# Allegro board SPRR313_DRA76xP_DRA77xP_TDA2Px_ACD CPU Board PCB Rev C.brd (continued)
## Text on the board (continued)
User.17: DATE | DESIGN ENGR | PROJECT ENGR | ENGR MGR | NEXT ASSEMBLY | APPROVED | CHECKED | DRAFTING | ENGR | NONE | 1 OF 1 | VIEW | SCALE: NONE | LAYER 7 | LAYER 8 | LAYER 9 | LAYER 10 | LAYER 11 | LAYER 12 | LAYER 13 | LAYER 14 | LAYER 15 | LAYER 16 | LAYER 1 | LAYER 2 | 1.  TOTAL BOARD THICKNESS SHALL BE .080 +/- 10% INCHES. | 2.  REFER TO STACKUP DRAWING FOR COPPER WEIGHT. | 4.  SOLDERMASK ON BOTH SIDES OF THE BOARD SHALL BE S.M.O.B.C., LPI, COLOR GREEN. | 3.  MINIMUM CLEARANCE ON THE BOARD SHALL BE 3.0 MILS. | 5.  PLATED THRU HOLE SIZE TOLERANCES SHALL BE +/- .003 INCH. | 6.  DRC'S MUST BE RUN ON THE GERBERS BEFORE BUILDING BOARDS UNLESS PRIOR | 9.  IMPEDANCE CONTROL: | 7.  FINISHED BOARD SHALL BE FREE OF BURRS ON EDGES. | 8.  SURFACE FINISH SHALL BE IMMERSION GOLD. | AVERAGE COPPER ON THE WALL OF THE | PLATED HOLE SHALL BE PER IPC CLASS 2. | ALL MATERIAL SHALL BE NEMA GRADE FR-4 OR EQUIVALENT. (Tg>=170 DEG. C) | UNPLATED THRU HOLE SIZE TOLERANCES SHALL BE +/- .002 INCH. | MINIMUM TRACE WIDTH ON THE BOARD SHALL BE 3.0 MILS. | APPROVAL IS GIVEN IN WRITING. | REFER TO STACKUP DRAWING FOR IMPEDANCE CONTROL. | NOTES: UNLESS OTHERWISE SPECIFIED | A | A-A
User.18: C100 | R534 | R533 | R535 | R483 | C352 | C347 | C541 | C528 | C484 | C502 | C517 | C504 | C509 | C516 | C477 | C507 | C490 | C491 | C497 | C469 | C508 | C518 | C467 | C498 | C486 | C403 | C343 | R709 | C407 | R513 | R537 | R514 | R516 | C462 | C520 | C458 | C457 | C519 | C471 | C388 | C489 | C512 | C386 | C481 | C495 | C468 | C485 | C475 | C480 | R271 | R273 | C186 | R272 | R274 | C187 | TP64 | R292 | TP61 | TP45 | TP39 | TP52 | R67 | C84 | R736 | R735 | C136 | C96 | C137 | C385 | TP8 | R261 | TP7 | TP10 | TP50 | R256 | C692 | R245 | TP11 | TP51 | TP53 | R658 | TP58 | R237 | R243 | TP14 | TP56 | R231 | U120 | R259 | R263 | TP60 | TP21 | TP26 | R258 | TP19 | TP34 | TP42 | TP43 | C142 | R215 | R553 | C380 | C375 | C353 | C339 | C338 | C432 | C346 | C354 | C341 | R639 | R648 | R655 | R662 | C342 | R395 | R398 | R661 | R666 | C691 | R663 | R640 | R649 | R656 | R542 | R545 | R550 | R556 | R563 | R571 | R582 | R602 | R609 | R613 | R543 | R546 | R551 | R586 | R595 | R598 | R611 | R614 | R572 | R557 | R564 | C649 | R544 | R547 | R552 | R370 | R375 | R377 | R381 | C104 | C412 | C418 | C425 | R632 | C460 | C548 | R376 | C384 | C413 | C419 | C426 | C436 | C368 | C465 | C556 | C367 | C365 | C650 | C483 | C473 | R386 | C265 | C414 | C420 | C427 | C549 | C396 | C400 | C557 | C255 | C369 | C366 | C474 | C466 | C94 | C253 | C91 | R382 | C370 | C260 | C118 | C119 | C392 | R618 | R624 | C92 | C391 | C526 | C482 | C542 | C437 | C444 | C506 | C361 | C501 | C249 | C248 | C245 | C246 | C242 | C478 | R538 | C492 | C439 | C505 | C463 | C127 | C510 | C422 | C429 | C110 | R587 | C479 | C448 | C201 | R214 | TP63 | TP48 | R714 | TP27 | C126 | TP55 | R738 | R740 | R742 | R744 | R746 | R748 | R737 | R739 | R741 | R743 | R745 | R747 | C32 | C171 | R288 | C178 | C185 | R731 | R131 | TP54 | TP59 | R730 | R732 | R110 | R111 | TP9 | R112 | R113 | R114 | R115 | R269 | C159 | R116 | C163 | R289 | TP29 | R120 | R121 | R122 | R123 | R124 | R125 | R191 | R209 | R210 | R211 | C433 | C99 | R193 | C431 | C134 | C101 | C141 | C102 | C103 | R201 | R518 | R708 | C680 | C376 | C379 | R622 | R18 | R16 | R15 | R700 | C642 | C628 | C636 | C664 | C651 | C666 | C667 | C668 | C669 | C562 | C644 | C595 | C630 | R694 | C615 | C652 | C629 | C637 | C401 | R629 | C674 | R625 | C675 | R378 | C523 | C399 | C676 | C677 | C247 | C355 | R399 | C364 | C395 | C500 | C356 | C438 | C496 | C493 | C494 | C537 | C390 | C359 | C363 | C372 | C393 | C445 | C360 | C394 | C398 | C524 | C442 | C90 | C487 | C443 | C397 | C456 | C529 | C89 | C373 | C449 | C530 | C602 | C362 | C589 | C374 | C461 | C371 | C470 | C464 | C402 | 1 | U17 | R291 | J16 | R244 | J2 | TP46 | TP49 | GND | U56 | 2 | USB-ID | U11 | SW1 | C149 | CAN1 | U16 | U12 | C155 | R129 | R133 | R136 | R137 | R139 | 12V-FAN | TP4 | R104 | J7 | R277 | C179 | R98 | R99 | R293 | R178 | U74 | U35 | U54 | C39 | R75 | U41 | J9 | J10 | J12 | TP5 | U48 | C36 | C31 | A1 | U46 | TP65 | TP6 | R200 | R196 | L4 | DCAN1 | JP1 | U36 | U43 | U1 | U9 | C68 | C70 | LEOPARD IMAGING | R27 | R185 | R7 | R1 | T1 | C210 | C73 | C75 | R6 | TP2 | PB/WAKE | Y5 | RU24 | U65 | C203 | C262 | R154 | C80 | Y3 | L8 | C87 | R179 | C682 | C211 | A9 | T9 | USB1 | E1 | C64 | C65 | C106 | E2 | RU31 | C681 | C212 | C113 | R722 | RU40 | E3 | U66 | E9 | C204 | Y6 | U26 | R30 | R33 | R39 | R41 | R47 | R52 | R190 | C213 | R195 | C143 | U15 | R66 | R68 | C107 | C148 | C83 | C59 | U10 | C194 | R96 | C43 | C214 | R61 | C37 | AH1 | AH28 | C40 | R97 | R31 | R34 | R40 | R42 | R48 | R53 | C34 | BGA WITHOUT SKT OUTLINE | U67 | C205 | R183 | U27 | RN2 | C55 | RN6 | RN4 | ETHERNET 0 | C175 | C180 | C165 | RN1 | C147 | U7 | R727 | R728 | R465 | C169 | R729 | R444 | C177 | C184 | R725 | TP12 | R28 | C293 | R468 | C199 | C25 | C26 | A28 | C44 | U68 | C21 | R726 | U18 | R72 | R73 | C41 | C195 | Y1 | E4 | C85 | R132 | R43 | R49 | R54 | ETHERNET 1 | E5 | C24 | R718 | SW2 | R128 | R242 | R56 | TP25 | R44 | R50 | R55 | C67 | R37 | R130 | C30 | E6 | R224 | TP16 | TP20 | TP13 | TP15 | R221 | U69 | R156 | C18 | R38 | RU19 | C196 | C146 | R188 | R189 | R197 | R198 | R202 | R212 | R217 | R235 | R248 | U62 | TP17 | DCAN2 | R199 | R203 | R213 | R218 | R220 | R225 | R232 | RU21 | R717 | JP3 | U61 | C98 | C122 | R2 | U6 | U25 | C135 | R5 | C4 | R286 | R270 | C14 | C176 | U38 | C12 | R3 | R229 | R233 | R268 | R240 | C15 | RU49 | C23 | C69 | C82 | R247 | L1 | JTAG | U2 | R754 | C16 | C2 | R181 | TP62 | R46 | C35 | U39 | R4 | C29 | U118 | U57 | 19 | U14 | R22 | DS1 | DS2 | DS3 | L13 | L3 | U3 | U58 | TP24 | R149 | TP32 | RU5 | E7 | DS4 | LCD CONNECTOR | C60 | L6 | C7 | L9 | R11 | J4 | E8 | C74 | R126 | USER | LEDS | R257 | R260 | R262 | R266 | R144 | R143 | L10 | TP31 | C131 | R472 | C76 | L11 | L19 | C47 | TP30 | U59 | R151 | Y4 | Q1 | Q3 | U37 | F1 | Q4 | R145 | C78 | U51 | Q2 | R147 | R281 | R146 | R234 | R239 | C133 | R287 | U8 | C97 | U55 | C153 | L21 | R440 | R449 | R127 | U47 | TP3 | C51 | C684 | C72 | C77 | C61 | L7 | R619 | R569 | R579 | R585 | R594 | R599 | R601 | R604 | R610 | R612 | R710 | R461 | C304 | C536 | R450 | R701 | C299 | C377 | C349 | U105 | C513 | C329 | C316 | R456 | C63 | C435 | C301 | C306 | R463 | C330 | R580 | R702 | C62 | R453 | C305 | C309 | R697 | C647 | R654 | R659 | R664 | R668 | U90 | R475 | R672 | Q5 | C302 | C326 | R451 | R671 | R464 | C307 | C327 | C215 | C568 | R675 | C575 | C558 | R660 | U91 | R673 | R422 | R423 | R426 | R638 | R647 | R665 | R414 | C328 | R428 | R749 | R674 | R676 | R677 | R682 | R383 | R384 | C236 | R750 | C216 | U106 | R567 | R35 | R751 | C488 | C459 | R332 | C318 | C235 | C333 | C378 | C410 | R474 | C350 | RU82 | U22 | R391 | R596 | C251 | R623 | U107 | R364 | R458 | C241 | U98 | R401 | U102 | U119 | U92 | R392 | U97 | U77 | RU88 | C476 | R407 | C274 | C280 | R427 | R433 | R17 | R343 | C383 | U78 | RU93 | C321 | C308 | C334 | RU103 | RU108 | C601 | C626 | C634 | R685 | R688 | U79 | R345 | R466 | R340 | R14 | C310 | R641 | R626 | C298 | R459 | R719 | R467 | 40 | R652 | C573 | U83 | C665 | 119 | EXP_P3 | R657 | 120 | R653 | R296 | R540 | U115 | R294 | U80 | C294 | R755 | R634 | R635 | R627 | R651 | C670 | 39 | R650 | R354 | R358 | R360 | R366 | R371 | C105 | R394 | R396 | R397 | R400 | R720 | R297 | R379 | R385 | R388 | R390 | R633 | R314 | RU94 | C453 | C673 | R380 | C95 | C322 | C226 | C108 | R350 | R355 | R359 | R361 | R367 | R372 | C93 | R330 | R328 | U116 | C678 | R298 | R436 | R295 | C616 | C631 | U28 | C643 | C627 | C635 | C599 | R299 | RN11 | C311 | C284 | R684 | R320 | R687 | R689 | C323 | R469 | U84 | C227 | C640 | RN17 | RN13 | R441 | R329 | R331 | C578 | C590 | R470 | C312 | R307 | C283 | C632 | U72 | C454 | R693 | R721 | C263 | C282 | C270 | R541 | C217 | C267 | R347 | C625 | C633 | C641 | C514 | RU96 | C324 | Y7 | C521 | R352 | C563 | C451 | C258 | C580 | C250 | R362 | R368 | R373 | C597 | C610 | C623 | C522 | R691 | C511 | C452 | C559 | C440 | C348 | C612 | U70 | C117 | R216 | R480 | C336 | R363 | R369 | R374 | C600 | C313 | R204 | C618 | R439 | R471 | C416 | C423 | R530 | R620 | C358 | EXP_P1 | R529 | C611 | R531 | R605 | C417 | C424 | R692 | R300 | RN9 | U73 | R415 | C613 | C624 | R308 | C256 | C266 | C264 | R321 | C261 | R448 | C583 | R630 | R322 | RN10 | R71 | L23 | RU89 | R353 | C619 | R532 | C638 | C605 | C268 | R301 | R481 | R305 | R421 | C254 | R581 | R669 | R584 | C1 | C525 | R645 | R600 | C257 | R713 | R593 | C446 | R603 | C230 | R615 | C547 | C331 | U112 | R528 | R517 | R597 | R515 | R539 | C275 | U110 | C279 | C288 | C604 | C345 | R568 | C335 | C411 | C405 | C332 | C292 | R325 | U114 | R323 | U104 | C658 | C579 | R460 | C351 | R617 | R324 | C607 | C515 | R326 | C272 | C532 | AUSTIN,TEXAS 78756 | 4410 SHOALWOOD | (512)260-5778 | C188 | C192 | C202 | L20 | R255 | R21 | R275 | R219 | R227 | C130 | C152 | C646 | R478 | R339 | R536 | R548 | C572 | TP22 | TP44 | R76 | 100 | RU13 | U64 | U63 | R241 | R290 | JP2 | U75 | 99 | FL5 | TP47 | R106 | R715 | C150 | R278 | R282 | TP23 | R148 | R279 | R283 | R222 | FL6 | R280 | R284 | R276 | C157 | R285 | Y2 | FL7 | U50 | B1 | FL8 | R157 | C3 | C42 | HDMI | C123 | C66 | SW7 | R29 | C79 | C259 | C120 | C86 | R58 | R59 | R62 | C125 | R63 | L12 | FL1 | R64 | R65 | R79 | C124 | C128 | FL2 | DAUGHTER CARD | C193 | TP57 | C182 | R60 | CONN1 | R78 | U44 | R77 | FL3 | R223 | RU42 | R267 | C183 | FL4 | R177 | C53 | R182 | R74 | R184 | R36 | C27 | R100 | R107 | C48 | RU32 | TP37 | R101 | R108 | TP1 | R158 | C206 | R102 | C164 | R103 | R160 | C58 | TP38 | C207 | R161 | R163 | R164 | R165 | C56 | R109 | R166 | TP40 | R105 | R167 | C545 | C197 | C57 | R168 | C450 | R733 | RU33 | R169 | C17 | R170 | C160 | R442 | C20 | C28 | C54 | R171 | C46 | R443 | R26 | R172 | U109 | R173 | R69 | R174 | C22 | C111 | C138 | R175 | C389 | C109 | U117 | C158 | R32 | R176 | C112 | C387 | C139 | R80 | C162 | C189 | C33 | C38 | R81 | R82 | C140 | R236 | C170 | C198 | R24 | TP28 | R83 | C161 | TP18 | TP33 | R84 | R85 | TP35 | C19 | C200 | RU4 | R86 | C145 | DAUGHTER | CARD | U60 | RU29 | CONN3 | U20 | C190 | R87 | R117 | TP36 | C172 | R88 | R118 | R119 | C208 | RN3 | RN5 | RN7 | RU30 | U121 | C166 | C181 | C209 | C129 | C167 | C9 | R246 | R264 | R180 | R265 | C88 | R230 | SW3 | PWR-RESET | CPU-RESET | C10 | R89 | C11 | R90 | R716 | R91 | R92 | 20 | L2 | C685 | R93 | L15 | L17 | C690 | R8 | R94 | R205 | C5 | U53 | R95 | MIC IN | R206 | C6 | R207 | R208 | C689 | C683 | C71 | TP41 | C121 | R194 | R192 | P10 | R134 | C8 | LINE IN | C52 | C13 | R20 | R10 | R9 | C115 | R140 | P11 | C173 | R153 | R13 | C45 | R12 | L18 | LINE OUT | C49 | C116 | R152 | C151 | C50 | C81 | C168 | C114 | L14 | L16 | R138 | P12 | L22 | SW8 | U34 | R155 | R135 | C132 | R249 | PMIC | R250 | R251 | R252 | 5 | R253 | R254 | HEADPHONE | P13 | PWR-INA | R696 | R573 | R574 | R575 | R576 | R577 | R578 | C303 | C295 | R642 | C409 | C314 | R683 | R643 | C565 | R454 | R678 | R455 | C566 | R644 | R142 | C300 | R680 | C567 | R679 | U101 | R457 | R141 | R681 | R549 | C408 | C430 | R476 | C381 | R338 | C317 | R588 | C231 | R589 | C232 | R590 | C234 | R333 | R565 | C434 | R591 | C543 | R566 | R592 | C228 | R570 | R404 | R405 | C252 | C229 | C320 | C273 | R406 | C269 | R753 | R429 | R417 | C441 | C499 | C544 | R327 | R473 | C233 | C319 | R304 | R703 | R554 | C290 | R410 | C297 | R19 | R704 | R555 | RU99 | C421 | R341 | R583 | R616 | R342 | R698 | C428 | R686 | R705 | R752 | R706 | R699 | R344 | R707 | C653 | C660 | RU111 | RU113 | C661 | TP66 | RN12 | RN14 | RN16 | R724 | C550 | C592 | C551 | C552 | R670 | C581 | C224 | C315 | R667 | R310 | R621 | R309 | R311 | C553 | R402 | R312 | C554 | R313 | C218 | C555 | R403 | R346 | C219 | C585 | C239 | C671 | C220 | C238 | C672 | C593 | R349 | U85 | R484 | R408 | C582 | R485 | R486 | R186 | R409 | R487 | C271 | R488 | C281 | R357 | R489 | C225 | R490 | C455 | R435 | C586 | R491 | R446 | R315 | RU95 | R492 | C679 | R447 | C596 | R695 | C645 | R493 | C561 | R316 | R437 | C221 | R494 | R317 | R438 | C655 | R495 | R318 | C222 | C289 | R496 | C656 | R319 | R497 | C657 | C223 | R498 | C654 | R499 | R500 | C662 | C285 | R501 | C584 | R303 | R502 | C663 | RN15 | R306 | R503 | C576 | R432 | R348 | R504 | C564 | R302 | C237 | R505 | C614 | R723 | C577 | R506 | C571 | C240 | R507 | C608 | R508 | C574 | R387 | R509 | C609 | R510 | C591 | R511 | C243 | C603 | R512 | C617 | C406 | R525 | C570 | C621 | R526 | C382 | C357 | R527 | C337 | C415 | C538 | R365 | C539 | C587 | C606 | C639 | U71 | RN8 | C533 | C622 | R356 | C598 | C534 | C535 | C296 | C594 | R636 | R631 | R637 | R416 | C588 | R70 | C340 | C325 | R712 | R519 | R711 | R690 | R628 | C344 | C404 | C447 | R646 | C540 | R479 | R559 | C527 | R560 | R561 | C531 | R562 | R420 | R520 | R521 | R413 | R434 | R522 | C659 | R523 | C472 | R524 | C291 | R462 | C503 | C278 | U100 | R558 | C546 | C174 | C156 | C191 | C154 | R238 | R150 | R226 | R228 | R187 | C144 | C620 | R606 | R607 | R608 | R482 | R477 | C648 | C569 | C560 | TURNING CONCEPT | INTO REALITY | OUT | P8 | P4 | J11 | P7 | PCIe CONNECTOR | P2 | J5 | USB2 | ETHERNET | AREA | U52 | P5 | P6 | J14 | J13 | DC | POWER | AUDIO | J3 | U23 | INTERFACE | J15 | LCD | DATE | DESIGN ENGR | PROJECT ENGR | ENGR MGR | NEXT ASSEMBLY | APPROVED | CHECKED | DRAFTING | ENGR | EXP_P2 | EXPANSION | 1 OF 1 | P9 | SATA | P3 | J1 | TERMINAL | P1 | SW4 | SW6 | FPD-LINK | U45 | J8 | SW5 | USERCONFIG | MICRO-SD | P14 | COM MODULE | MLB/MLBP | ASSY 516580 REV | VAYU EVM | XC5777X CPU BOARD | S/N | SYSBOOT | [0-15] | + | ASSEMBLY SOLDER SIDE
User.19: AUSTIN,TEXAS 78756 | 4410 SHOALWOOD | (512)260-5778 | TURNING CONCEPT | INTO REALITY | NONE
User.20: AUSTIN,TEXAS 78756 | 4410 SHOALWOOD | (512)260-5778 | TURNING CONCEPT | INTO REALITY
User.21: 1 | J18 | 2 | J19 | 41 | 42 | J17 | 79 | 80 | 119 | 120
User.22: 1. All board outlines shall be .020 in width. | 2. All other lines shall be .012 in width. | 3. Note and misc. text shall be text block 10. | 4. View and description text shall be text block 16. | 5. Make sure that there is not any double dimensioning, | 6. Check all notes to make sure that they apply and are correct. | 7. Make sure that layer stack-up is correct. | label (REF) dim when needed.
User.23: 91.0x40.0 | 98.0x40.0 | 118.0x40.0 | FIGURE | SIZE | 8.0 | 10.0 | 12.0 | 13.0 | 29.0 | 35.0 | 38.0 | 39.0 | 40.0 | 51.0 | 53.0 | 55.0 | 62.0 | 64.96 | 67.0 | 95.0 | 125.0 | 34.0 | 41.0 | 47.0 | 61.0 | 63.0 | 69.0 | 93.0 | 126.0 | PLATED | NON-PLATED | DRILL CHART | ALL UNITS ARE IN MILS | QTY | 3272 | 2311 | 231 | 27 | 7 | 4 | 34 | 44 | 6 | 2 | 1 | 5 | 10 | 8 | TOL | NOTE
User.26: P15 | 2 | 1 | CSI2 CAMERA
